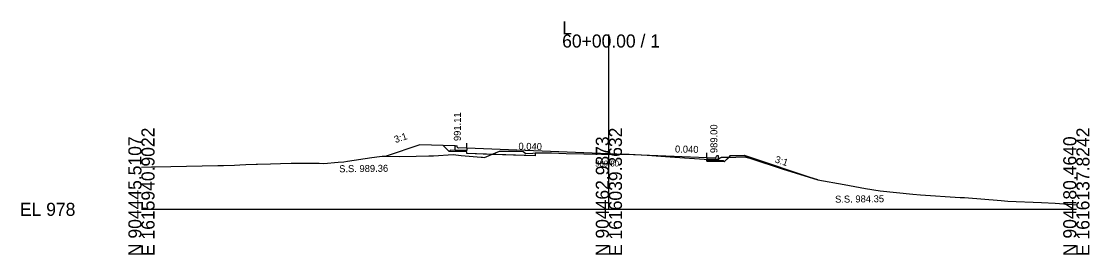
# Model space of a CAD drawing. Extents: x 1009 to 7438, y -1586 to 7964.
# Drawn here: x 5009.2 to 5237.7, y 7914 to 7963.9 of the extents above; entities that cross this region are included whole.
import ezdxf

# ---------------------------------------------------------------- set-up
doc = ezdxf.new("R2010")
doc.units = 0
for name, color, linetype in [('Exist Cross Section Cell', 7, 'Continuous'), ('Exist XS Center Line Elevation Label', 7, 'Continuous'), ('Exist XS Ground Line', 7, 'Continuous'), ('Prop XS Earthwork Shape', 7, 'Continuous'), ('Prop XS EOT Tick Mark', 7, 'Continuous'), ('Prop XS Finish Grade', 7, 'Continuous'), ('Prop XS Finish Grade CurbGutter', 7, 'Continuous'), ('Prop XS Finish Grade Earthwork', 7, 'Continuous'), ('Prop XS Finish Grade Pavement', 7, 'Continuous'), ('Prop XS Hydro Elevations', 7, 'Continuous'), ('Prop XS Pvmt Edge Slope', 7, 'Continuous'), ('Prop XS SE Text', 7, 'Continuous'), ('Prop XS Side Slope Text', 7, 'Continuous'), ('Prop XS SS Elevation Text', 7, 'Continuous'), ('Prop XS Subgrade CurbGutter', 7, 'Continuous'), ('Prop XS Subgrade Earthwork', 7, 'Continuous')]:
    doc.layers.add(name, color=color, linetype=linetype)

msp = doc.modelspace()

# ---------------------------------------------------------------- linework, layer by layer
at = {"layer": 'Exist Cross Section Cell'}
for p, q in [((5134.89, 7923.73), (5134.89, 7961.14)), ((5034.89, 7923.73), (5134.89, 7923.73)), ((5134.89, 7923.73), (5234.89, 7923.73))]:
    msp.add_line(p, q, dxfattribs=at)
at = {"layer": 'Exist XS Ground Line'}
for p, q in [((5078.98, 7934.01), (5084.14, 7934.82)), ((5084.14, 7934.82), (5085.85, 7935.05)), ((5085.85, 7935.05), (5086.38, 7935.13)), ((5086.38, 7935.13), (5087.62, 7935.07)), ((5087.62, 7935.07), (5090.09, 7935.02)), ((5090.09, 7935.02), (5093.66, 7935.1)), ((5093.66, 7935.1), (5096.39, 7935.17)), ((5096.39, 7935.17), (5097.38, 7935.17)), ((5097.38, 7935.17), (5101.54, 7935.47)), ((5101.54, 7935.47), (5103.26, 7935.28)), ((5103.26, 7935.28), (5107.53, 7934.87)), ((5107.53, 7934.87), (5107.83, 7934.86)), ((5107.83, 7934.86), (5108.3, 7934.83)), ((5108.3, 7934.83), (5109.75, 7935.48)), ((5109.75, 7935.48), (5111.48, 7936.2)), ((5111.48, 7936.2), (5115.16, 7936.15)), ((5115.16, 7936.15), (5116.53, 7936.13)), ((5116.53, 7936.13), (5117.13, 7935.68)), ((5117.13, 7935.68), (5118.59, 7935.78)), ((5118.59, 7935.78), (5119.14, 7935.81)), ((5119.14, 7935.81), (5120.31, 7935.8)), ((5120.31, 7935.8), (5122.59, 7935.79)), ((5122.59, 7935.79), (5125.78, 7935.7)), ((5125.78, 7935.7), (5133.29, 7935.54)), ((5133.29, 7935.54), (5134.89, 7935.53)), ((5134.89, 7935.53), (5135.2, 7935.52)), ((5135.2, 7935.52), (5139.25, 7935.51)), ((5139.25, 7935.51), (5143.09, 7935.31)), ((5143.09, 7935.31), (5144.99, 7935.2)), ((5144.99, 7935.2), (5148.96, 7934.92)), ((5148.96, 7934.92), (5156.37, 7934.42)), ((5158.1, 7934.36), (5158.88, 7934.81)), ((5158.88, 7934.81), (5162.05, 7934.89)), ((5162.05, 7934.89), (5163.92, 7934.93)), ((5163.92, 7934.93), (5164.75, 7934.76)), ((5164.75, 7934.76), (5165.27, 7934.63)), ((5034.89, 7932.75), (5037.01, 7932.82)), ((5037.01, 7932.82), (5037.41, 7932.83)), ((5037.41, 7932.83), (5037.83, 7932.84)), ((5037.83, 7932.84), (5051.22, 7933.09)), ((5051.22, 7933.09), (5052.45, 7933.11)), ((5052.45, 7933.11), (5054.77, 7933.17)), ((5054.77, 7933.17), (5055.94, 7933.24)), ((5055.94, 7933.24), (5057.25, 7933.34)), ((5057.25, 7933.34), (5059.42, 7933.4)), ((5059.42, 7933.4), (5059.74, 7933.41)), ((5059.74, 7933.41), (5062.49, 7933.45)), ((5062.49, 7933.45), (5064.67, 7933.52)), ((5064.67, 7933.52), (5066.95, 7933.58)), ((5066.95, 7933.58), (5070.87, 7933.57)), ((5070.87, 7933.57), (5072.92, 7933.57)), ((5072.92, 7933.57), (5073.88, 7933.55)), ((5073.88, 7933.55), (5076.98, 7933.79)), ((5076.98, 7933.79), (5078.15, 7933.88)), ((5078.15, 7933.88), (5078.98, 7934.01)), ((5156.37, 7934.42), (5157.49, 7934.38)), ((5157.49, 7934.38), (5158.1, 7934.36)), ((5165.27, 7934.63), (5172.2, 7932.3)), ((5172.2, 7932.3), (5179.6, 7930.07)), ((5179.6, 7930.07), (5185.19, 7929.02)), ((5185.19, 7929.02), (5189.76, 7928.18)), ((5189.76, 7928.18), (5192.95, 7927.7)), ((5192.95, 7927.7), (5199.92, 7926.99)), ((5199.92, 7926.99), (5201.58, 7926.84)), ((5201.58, 7926.84), (5210.07, 7926.29)), ((5210.07, 7926.29), (5210.93, 7926.23)), ((5210.93, 7926.23), (5218.83, 7925.6)), ((5218.83, 7925.6), (5220.23, 7925.51)), ((5220.23, 7925.51), (5227.45, 7925.21)), ((5227.45, 7925.21), (5230.39, 7925.06)), ((5230.39, 7925.06), (5234.89, 7924.68))]:
    msp.add_line(p, q, dxfattribs=at)
at = {"layer": 'Prop XS Earthwork Shape'}
for points in [[(5097.38, 7935.17), (5101.54, 7935.47), (5103.26, 7935.28), (5107.53, 7934.87), (5107.83, 7934.86), (5108.3, 7934.83), (5109.75, 7935.48), (5104.47, 7935.67), (5104.47, 7936.06), (5100.72, 7936.12), (5099.44, 7937.39), (5094.47, 7937.5), (5087.23, 7935.08), (5087.62, 7935.07), (5090.09, 7935.02), (5093.66, 7935.1), (5096.39, 7935.17)], [(5119.14, 7935.81), (5119.13, 7935.15), (5109.75, 7935.48), (5111.48, 7936.2), (5115.16, 7936.15), (5116.53, 7936.13), (5117.13, 7935.68), (5118.59, 7935.78)], [(5158.34, 7934.2), (5159.34, 7934.18), (5159.59, 7933.93), (5160.52, 7934.85), (5158.88, 7934.81), (5158.34, 7934.5)], [(5160.52, 7934.85), (5160.93, 7935.26), (5163.84, 7935.33), (5179.6, 7930.07), (5172.2, 7932.3), (5165.27, 7934.63), (5164.75, 7934.76), (5163.92, 7934.93), (5162.05, 7934.89)], [(5158.34, 7934.2), (5158.34, 7934.5), (5158.1, 7934.36), (5157.49, 7934.38), (5156.37, 7934.42), (5155.84, 7934.46), (5155.84, 7934.25)], [(5158.34, 7934.2), (5159.34, 7934.18), (5159.59, 7933.93), (5155.84, 7934), (5155.84, 7934.25)]]:
    msp.add_lwpolyline(points, close=True, dxfattribs=at)
at = {"layer": 'Prop XS EOT Tick Mark'}
for p, q in [((5104.47, 7936.89), (5104.47, 7937.89)), ((5155.84, 7934.83), (5155.84, 7935.83))]:
    msp.add_line(p, q, dxfattribs=at)
at = {"layer": 'Prop XS Finish Grade'}
msp.add_line((5101.97, 7937.34), (5099.44, 7937.39), dxfattribs=at)
at = {"layer": 'Prop XS Finish Grade CurbGutter'}
for p, q in [((5101.97, 7937.34), (5102.22, 7937.34)), ((5102.22, 7937.34), (5102.34, 7937.3)), ((5102.44, 7937.21), (5102.34, 7937.3)), ((5102.5, 7936.96), (5102.44, 7937.21)), ((5102.59, 7936.87), (5102.5, 7936.96)), ((5102.72, 7936.84), (5102.59, 7936.87)), ((5104.47, 7936.89), (5102.72, 7936.84)), ((5155.84, 7934.83), (5157.59, 7934.73)), ((5157.59, 7934.73), (5157.72, 7934.75)), ((5157.72, 7934.75), (5157.81, 7934.84)), ((5157.81, 7934.84), (5157.88, 7935.09)), ((5157.88, 7935.09), (5157.97, 7935.18)), ((5158.09, 7935.21), (5157.97, 7935.18)), ((5158.34, 7935.21), (5158.09, 7935.21))]:
    msp.add_line(p, q, dxfattribs=at)
at = {"layer": 'Prop XS Finish Grade Earthwork'}
for p, q in [((5094.47, 7937.5), (5087.23, 7935.08)), ((5099.44, 7937.39), (5094.47, 7937.5)), ((5160.93, 7935.26), (5163.84, 7935.33)), ((5163.84, 7935.33), (5179.6, 7930.07))]:
    msp.add_line(p, q, dxfattribs=at)
at = {"layer": 'Prop XS Finish Grade Pavement'}
for p, q in [((5104.47, 7936.89), (5134.89, 7935.67)), ((5134.89, 7935.67), (5155.84, 7934.83))]:
    msp.add_line(p, q, dxfattribs=at)
at = {"layer": 'Prop XS Pvmt Edge Slope'}
for p, q in [((5100.97, 7936.36), (5100.72, 7936.12)), ((5101.97, 7936.35), (5100.97, 7936.36)), ((5158.34, 7934.2), (5159.34, 7934.18)), ((5159.34, 7934.18), (5159.59, 7933.93))]:
    msp.add_line(p, q, dxfattribs=at)
at = {"layer": 'Prop XS Subgrade CurbGutter'}
for p, q in [((5101.97, 7936.35), (5101.97, 7937.34)), ((5104.47, 7936.31), (5101.97, 7936.35)), ((5104.47, 7936.89), (5104.47, 7936.31)), ((5155.84, 7934.83), (5155.84, 7934.25)), ((5158.34, 7934.2), (5158.34, 7935.21)), ((5155.84, 7934.25), (5158.34, 7934.2))]:
    msp.add_line(p, q, dxfattribs=at)
at = {"layer": 'Prop XS Subgrade Earthwork'}
for p, q in [((5100.72, 7936.12), (5099.44, 7937.39)), ((5104.47, 7936.06), (5100.72, 7936.12)), ((5104.47, 7935.67), (5104.47, 7936.06)), ((5119.13, 7935.15), (5104.47, 7935.67)), ((5119.14, 7935.81), (5119.13, 7935.15)), ((5159.59, 7933.93), (5160.93, 7935.26)), ((5155.84, 7934.46), (5155.84, 7934)), ((5155.84, 7934), (5155.84, 7934)), ((5155.84, 7934), (5159.59, 7933.93))]:
    msp.add_line(p, q, dxfattribs=at)

# ---------------------------------------------------------------- texts
at = {"layer": 'Exist Cross Section Cell'}
for s, p in [('L', (5124.89, 7961.14)), ('60+00.00 / 1', (5124.89, 7958.34)), ('EL 978', (5008.89, 7922.33))]:
    msp.add_text(s, height=2.8, dxfattribs=at).set_placement(p)
for s, p in [('E 1615940.9022', (5037.69, 7913.73)), ('E 1616039.3632', (5137.69, 7913.73)), ('E 1616137.8242', (5237.69, 7913.73)), ('N 904445.5107', (5034.89, 7913.73)), ('N 904462.9873', (5134.89, 7913.73)), ('N 904480.4640', (5234.89, 7913.73))]:
    msp.add_text(s, height=2.8, rotation=90, dxfattribs=at).set_placement(p)
at = {"layer": 'Exist XS Center Line Elevation Label'}
msp.add_text('989.80', height=1.25, dxfattribs=at).set_placement((5131.94, 7932.9))
at = {"layer": 'Prop XS Hydro Elevations'}
for s, p in [('991.11', (5103.22, 7938.34)), ('989.00', (5158.1, 7935.76))]:
    msp.add_text(s, height=1.5, rotation=90, dxfattribs=at).set_placement(p)
at = {"layer": 'Prop XS SE Text'}
for rotation, p in [(359.0652, (5115.53, 7936.48)), (358.8542, (5149.02, 7935.89))]:
    msp.add_text('0.040', height=1.5, rotation=rotation, dxfattribs=at).set_placement(p)
at = {"layer": 'Prop XS Side Slope Text'}
for rotation, p in [(18.4349, (5089.24, 7937.89)), (341.5651, (5170.28, 7933.81))]:
    msp.add_text('3:1', height=1.5, rotation=rotation, dxfattribs=at).set_placement(p)
at = {"layer": 'Prop XS SS Elevation Text'}
for s, p in [('S.S. 989.36', (5077.19, 7931.66)), ('S.S. 984.35', (5183.28, 7925.15))]:
    msp.add_text(s, height=1.5, rotation=0.5729, dxfattribs=at).set_placement(p)

doc.saveas('drawing.dxf')
